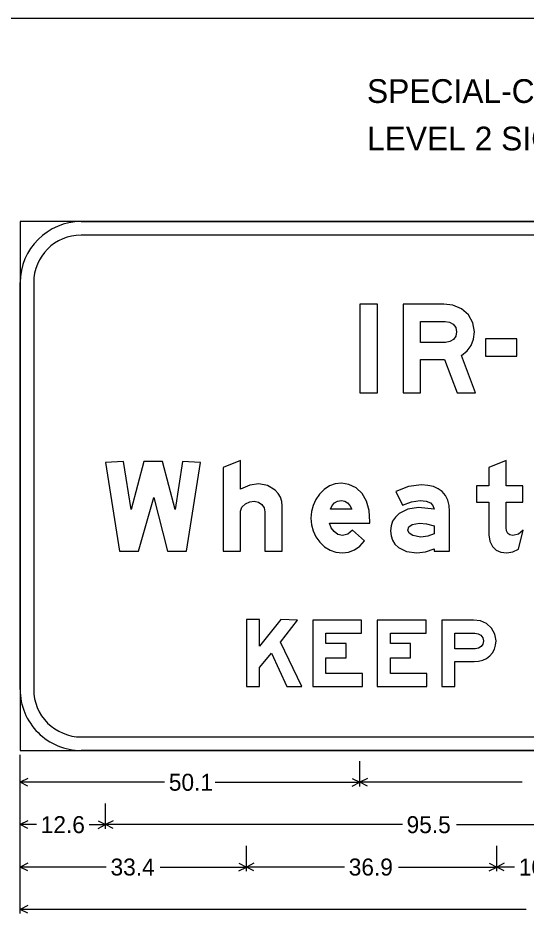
# Model space of a CAD drawing. Extents: x 1820207 to 1820557, y 740216 to 740315.
# Drawn here: x 1820485.52 to 1820488.52, y 740270.39 to 740275.74 of the extents above; entities that cross this region are included whole.
import ezdxf

# ---------------------------------------------------------------- set-up
doc = ezdxf.new("R2010")
doc.units = 0
for name, color, linetype in [('SC_Scratch2', 7, 'Continuous'), ('SC_Scratch3', 7, 'Continuous'), ('SH_Text', 7, 'Continuous')]:
    doc.layers.add(name, color=color, linetype=linetype)

msp = doc.modelspace()

# ---------------------------------------------------------------- linework, layer by layer
at = {"layer": 'SC_Scratch2'}
msp.add_lwpolyline([(1820476.451, 740275.7419), (1820506.951, 740275.7419), (1820506.951, 740254.7419), (1820476.451, 740254.7419)], close=True, dxfattribs=at)
at = {"layer": 'SC_Scratch3'}
for p, q in [((1820485.5321, 740270.4594), (1820485.5321, 740271.3969)), ((1820485.5321, 740271.2094), (1820485.5321, 740271.3594)), ((1820487.5348, 740271.2094), (1820487.5348, 740271.3594)), ((1820485.5768, 740271.2568), (1820485.5321, 740271.2344)), ((1820487.4901, 740271.2568), (1820487.5348, 740271.2344)), ((1820487.5795, 740271.2568), (1820487.5348, 740271.2344)), ((1820486.3841, 740271.2344), (1820485.5321, 740271.2344)), ((1820485.5768, 740271.212), (1820485.5321, 740271.2344)), ((1820486.6828, 740271.2344), (1820487.5348, 740271.2344)), ((1820487.4901, 740271.212), (1820487.5348, 740271.2344)), ((1820488.4925, 740271.2344), (1820487.5348, 740271.2344)), ((1820487.5795, 740271.212), (1820487.5348, 740271.2344)), ((1820485.5321, 740270.9594), (1820485.5321, 740271.1094)), ((1820486.0361, 740270.9594), (1820486.0361, 740271.1094)), ((1820485.5768, 740271.0068), (1820485.5321, 740270.9844)), ((1820485.6287, 740270.9844), (1820485.5321, 740270.9844)), ((1820485.5768, 740270.962), (1820485.5321, 740270.9844)), ((1820485.9395, 740270.9844), (1820486.0361, 740270.9844)), ((1820485.9914, 740271.0068), (1820486.0361, 740270.9844)), ((1820485.9914, 740270.962), (1820486.0361, 740270.9844)), ((1820486.0808, 740271.0068), (1820486.0361, 740270.9844)), ((1820487.7859, 740270.9844), (1820486.0361, 740270.9844)), ((1820486.0808, 740270.962), (1820486.0361, 740270.9844)), ((1820488.105, 740270.9844), (1820489.8548, 740270.9844)), ((1820485.5321, 740270.7094), (1820485.5321, 740270.8594)), ((1820486.8661, 740270.7094), (1820486.8661, 740270.8594)), ((1820488.3421, 740270.7094), (1820488.3421, 740270.8594)), ((1820485.5768, 740270.7568), (1820485.5321, 740270.7344)), ((1820486.0403, 740270.7344), (1820485.5321, 740270.7344)), ((1820485.5768, 740270.712), (1820485.5321, 740270.7344)), ((1820486.3579, 740270.7344), (1820486.8661, 740270.7344)), ((1820486.8214, 740270.7568), (1820486.8661, 740270.7344)), ((1820486.8214, 740270.712), (1820486.8661, 740270.7344)), ((1820486.9108, 740270.7568), (1820486.8661, 740270.7344)), ((1820487.4448, 740270.7344), (1820486.8661, 740270.7344)), ((1820486.9108, 740270.712), (1820486.8661, 740270.7344)), ((1820487.7634, 740270.7344), (1820488.3421, 740270.7344)), ((1820488.2974, 740270.7568), (1820488.3421, 740270.7344)), ((1820488.2974, 740270.712), (1820488.3421, 740270.7344)), ((1820488.3868, 740270.7568), (1820488.3421, 740270.7344)), ((1820488.4477, 740270.7344), (1820488.3421, 740270.7344)), ((1820488.3868, 740270.712), (1820488.3421, 740270.7344)), ((1820485.5768, 740270.5068), (1820485.5321, 740270.4844)), ((1820488.5169, 740270.4844), (1820485.5321, 740270.4844)), ((1820485.5768, 740270.462), (1820485.5321, 740270.4844))]:
    msp.add_line(p, q, dxfattribs=at)
for points in [[(1820485.5321, 740271.4219), (1820491.7721, 740271.4219), (1820491.7721, 740274.5419), (1820485.5321, 740274.5419), (1820485.5321, 740271.4219), (1820485.5321, 740271.4219), (1820485.5321, 740271.4219)], [(1820485.8921, 740274.5419), (1820491.4121, 740274.5419)], [(1820491.4121, 740274.4619), (1820485.8921, 740274.4619)], [(1820485.5321, 740271.7819), (1820485.5321, 740274.1819)], [(1820485.6121, 740274.1819), (1820485.6121, 740271.7819)], [(1820485.6121, 740274.1819), (1820485.6121, 740274.1819), (1820485.6121, 740274.1819)], [(1820485.8921, 740271.5019), (1820491.4121, 740271.5019)], [(1820485.8921, 740271.5019), (1820485.8921, 740271.5019), (1820485.8921, 740271.5019)], [(1820491.4121, 740271.4219), (1820485.8921, 740271.4219)]]:
    msp.add_lwpolyline(points, dxfattribs=at)
for points in [[(1820487.5348, 740273.5319), (1820487.6402, 740273.5319), (1820487.6402, 740274.055), (1820487.5348, 740274.055)], [(1820488.1342, 740273.7525), (1820488.1675, 740273.7792), (1820488.1914, 740273.8112), (1820488.2058, 740273.8486), (1820488.2106, 740273.8911), (1820488.2017, 740273.9442), (1820488.175, 740273.9913), (1820488.1345, 740274.028), (1820488.084, 740274.0497), (1820488.0302, 740274.055), (1820487.7908, 740274.055), (1820487.7908, 740273.5319), (1820487.8933, 740273.5319), (1820487.8933, 740273.7287), (1820488.035, 740273.7287), (1820488.1087, 740273.5319), (1820488.218, 740273.5319)], [(1820488.1061, 740273.8917), (1820488.1013, 740273.8665), (1820488.0872, 740273.8466), (1820488.066, 740273.8337), (1820488.0408, 740273.8293), (1820487.8933, 740273.8293), (1820487.8933, 740273.9524), (1820488.0385, 740273.9524), (1820488.0645, 740273.9482), (1820488.0864, 740273.9359), (1820488.1012, 740273.9165)], [(1820488.4607, 740273.8498), (1820488.2761, 740273.8498), (1820488.2761, 740273.7473), (1820488.4607, 740273.7473)], [(1820486.1189, 740272.5986), (1820486.2297, 740272.5986), (1820486.3203, 740272.9146), (1820486.4016, 740272.5986), (1820486.5123, 740272.5986), (1820486.5952, 740273.1216), (1820486.4903, 740273.1259), (1820486.446, 740272.8432), (1820486.3721, 740273.1259), (1820486.2612, 740273.1259), (1820486.1875, 740272.8432), (1820486.141, 740273.1259), (1820486.0361, 740273.1216)], [(1820486.7294, 740272.5986), (1820486.832, 740272.5986), (1820486.832, 740272.8332), (1820486.839, 740272.8566), (1820486.8603, 740272.8764), (1820486.8859, 740272.8883), (1820486.9128, 740272.8923), (1820486.9372, 740272.8876), (1820486.9574, 740272.8738), (1820486.9709, 740272.8535), (1820486.9755, 740272.8295), (1820486.9755, 740272.5986), (1820487.0775, 740272.5986), (1820487.0775, 740272.8649), (1820487.0747, 740272.8912), (1820487.067, 740272.9155), (1820487.0539, 740272.9376), (1820487.0358, 740272.9578), (1820486.9913, 740272.9851), (1820486.939, 740272.9942), (1820486.8872, 740272.9862), (1820486.832, 740272.9625), (1820486.832, 740273.1319), (1820486.7294, 740273.0915)], [(1820488.2228, 740272.8858), (1820488.2955, 740272.8858), (1820488.295, 740272.6939), (1820488.3019, 740272.6563), (1820488.317, 740272.6257), (1820488.3386, 740272.6042), (1820488.3668, 740272.5918), (1820488.4016, 740272.5884), (1820488.4379, 740272.5943), (1820488.4707, 740272.6093), (1820488.498, 740272.721), (1820488.4704, 740272.6984), (1820488.4379, 740272.6908), (1820488.4205, 740272.6938), (1820488.4082, 740272.7026), (1820488.4008, 740272.7171), (1820488.3984, 740272.7376), (1820488.3984, 740272.8858), (1820488.4971, 740272.8858), (1820488.4971, 740272.9837), (1820488.3984, 740272.9837), (1820488.3984, 740273.1319), (1820488.2955, 740273.092), (1820488.2955, 740272.9837), (1820488.2228, 740272.9837)], [(1820487.5633, 740272.6578), (1820487.491, 740272.7215), (1820487.4652, 740272.6984), (1820487.4325, 740272.6908), (1820487.406, 740272.6963), (1820487.383, 740272.7132), (1820487.366, 740272.7358), (1820487.3565, 740272.7626), (1820487.5948, 740272.7626), (1820487.5948, 740272.7715), (1820487.5902, 740272.8375), (1820487.5753, 740272.8926), (1820487.5496, 740272.9369), (1820487.5136, 740272.9705), (1820487.4713, 740272.9915), (1820487.4265, 740272.9986), (1820487.3897, 740272.9944), (1820487.3559, 740272.9822), (1820487.3251, 740272.9619), (1820487.2974, 740272.9337), (1820487.2751, 740272.9016), (1820487.2594, 740272.8676), (1820487.2498, 740272.8314), (1820487.2468, 740272.7931), (1820487.25, 740272.7537), (1820487.2597, 740272.7171), (1820487.2761, 740272.683), (1820487.299, 740272.6516), (1820487.3275, 740272.6237), (1820487.3594, 740272.604), (1820487.3944, 740272.5922), (1820487.4325, 740272.5884), (1820487.4692, 740272.5927), (1820487.5033, 740272.6056), (1820487.5345, 740272.6272)], [(1820487.9725, 740272.5986), (1820488.0646, 740272.5986), (1820488.0646, 740272.8314), (1820488.0617, 740272.8675), (1820488.0536, 740272.8992), (1820488.0396, 740272.9263), (1820488.0204, 740272.949), (1820487.9967, 740272.966), (1820487.9686, 740272.9783), (1820487.936, 740272.9858), (1820487.8991, 740272.9883), (1820487.8224, 740272.9783), (1820487.7476, 740272.9487), (1820487.7871, 740272.8681), (1820487.8395, 740272.8889), (1820487.8916, 740272.896), (1820487.9259, 740272.8928), (1820487.9509, 740272.8835), (1820487.9662, 740272.8678), (1820487.9725, 740272.846), (1820487.8805, 740272.855), (1820487.8184, 740272.8462), (1820487.7672, 740272.8197), (1820487.7447, 740272.7988), (1820487.7287, 740272.7748), (1820487.7191, 740272.7476), (1820487.7161, 740272.7171), (1820487.719, 740272.6876), (1820487.7278, 740272.6617), (1820487.7423, 740272.6391), (1820487.7628, 740272.6199), (1820487.811, 740272.5962), (1820487.8704, 740272.5884), (1820487.9233, 740272.5942), (1820487.9725, 740272.6117)], [(1820487.4873, 740272.8447), (1820487.3623, 740272.8447), (1820487.3719, 740272.8671), (1820487.3858, 740272.8832), (1820487.4041, 740272.8928), (1820487.4267, 740272.896), (1820487.4461, 740272.8928), (1820487.4626, 740272.8832), (1820487.4762, 740272.8671)], [(1820487.9725, 740272.7), (1820487.9367, 740272.6854), (1820487.8951, 740272.6806), (1820487.8472, 740272.6896), (1820487.8257, 740272.7037), (1820487.8186, 740272.7224), (1820487.8249, 740272.7414), (1820487.8436, 740272.7546), (1820487.8878, 740272.7626), (1820487.9281, 740272.7588), (1820487.9725, 740272.7473)], [(1820486.8661, 740271.7986), (1820486.9436, 740271.7986), (1820486.9436, 740271.9106), (1820487.0136, 740271.9952), (1820487.105, 740271.7986), (1820487.1924, 740271.7986), (1820487.0674, 740272.0618), (1820487.1675, 740272.1909), (1820487.069, 740272.1941), (1820486.9436, 740272.0378), (1820486.9436, 740272.1941), (1820486.8661, 740272.1941)], [(1820487.5509, 740271.8755), (1820487.3352, 740271.8755), (1820487.3352, 740271.9678), (1820487.4543, 740271.9678), (1820487.4543, 740272.0524), (1820487.3352, 740272.0524), (1820487.3352, 740272.114), (1820487.5454, 740272.114), (1820487.5454, 740272.1909), (1820487.2581, 740272.1909), (1820487.2581, 740271.7986), (1820487.5509, 740271.7986)], [(1820487.9309, 740271.8755), (1820487.7152, 740271.8755), (1820487.7152, 740271.9678), (1820487.8343, 740271.9678), (1820487.8343, 740272.0524), (1820487.7152, 740272.0524), (1820487.7152, 740272.114), (1820487.9254, 740272.114), (1820487.9254, 740272.1909), (1820487.6381, 740272.1909), (1820487.6381, 740271.7986), (1820487.9309, 740271.7986)], [(1820488.0181, 740271.7986), (1820488.095, 740271.7986), (1820488.095, 740271.9461), (1820488.2085, 740271.9461), (1820488.2351, 740271.9482), (1820488.2596, 740271.9546), (1820488.2817, 740271.9651), (1820488.3014, 740271.98), (1820488.3175, 740271.9982), (1820488.3291, 740272.0191), (1820488.3361, 740272.0425), (1820488.3385, 740272.0688), (1820488.3319, 740272.1081), (1820488.3124, 740272.1433), (1820488.2827, 740272.1708), (1820488.246, 740272.187), (1820488.2059, 740272.1909), (1820488.0181, 740272.1909)], [(1820488.095, 740272.0216), (1820488.095, 740272.114), (1820488.2136, 740272.114), (1820488.2328, 740272.1108), (1820488.2492, 740272.1016), (1820488.2604, 740272.087), (1820488.2642, 740272.0684), (1820488.2607, 740272.0495), (1820488.2504, 740272.0346), (1820488.2349, 740272.0249), (1820488.216, 740272.0216)]]:
    msp.add_lwpolyline(points, close=True, dxfattribs=at)
for centre, radius, start, end in [((1820485.8921, 740274.1819), 0.36, 90.0002, 179.9999), ((1820485.8921, 740274.1819), 0.28, 90.0002, 179.9998), ((1820485.8921, 740271.7819), 0.36, 179.9998, 270.0001), ((1820485.8921, 740271.7819), 0.28, 179.9999, 270.0001)]:
    msp.add_arc(centre, radius, start, end, dxfattribs=at)

# ---------------------------------------------------------------- texts
for s, p in [('50.1', (1820486.4091, 740271.1844)), ('12.6', (1820485.6537, 740270.9344)), ('95.5', (1820487.8109, 740270.9344)), ('33.4', (1820486.0653, 740270.6844)), ('36.9', (1820487.4698, 740270.6844)), ('10', (1820488.4727, 740270.6844))]:
    msp.add_text(s, height=0.1, dxfattribs=at).set_placement(p)
at = {"layer": 'SH_Text'}
for s, p in [('SPECIAL-C', (1820487.5774, 740275.2419)), ('LEVEL 2 SIGN - GROUND MOUNTED', (1820487.5774, 740274.9619))]:
    msp.add_text(s, height=0.14, dxfattribs=at).set_placement(p)

doc.saveas('drawing.dxf')
